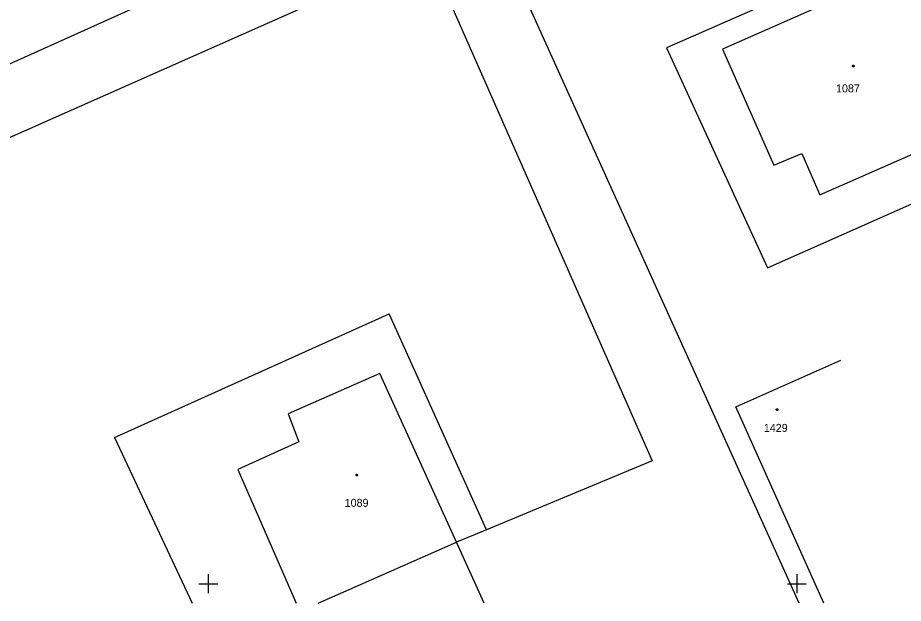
# Model space of a CAD drawing. Extents: x -772300 to -772183, y -1034101 to -1034019.
# Drawn here: x -772258.1 to -772220.48, y -1034100.83 to -1034075.93 of the extents above; entities that cross this region are included whole.
import ezdxf

# ---------------------------------------------------------------- set-up
doc = ezdxf.new("R2010")
doc.units = 0
for name, color, linetype in [('KM_hranice', 7, 'Continuous'), ('KM_kody_budov', 7, 'Continuous'), ('KM_parcelni_cisla', 7, 'Continuous'), ('KM_vnitrni_kresba', 7, 'Continuous'), ('souradnicova_sit', 7, 'Continuous')]:
    doc.layers.add(name, color=color, linetype=linetype)

msp = doc.modelspace()

# ---------------------------------------------------------------- linework, layer by layer
at = {"layer": 'KM_hranice'}
for p, q in [((-772237.52, -1034068.47), (-772299.808, -1034096.549)), ((-772224.901, -1034100.835), (-772237.97, -1034071.91)), ((-772276.27, -1034088.94), (-772240.68, -1034073.14)), ((-772240.68, -1034073.14), (-772231.15, -1034094.77)), ((-772221.31, -1034073.16), (-772230.54, -1034077.22)), ((-772230.54, -1034077.22), (-772226.24, -1034086.57)), ((-772226.24, -1034086.57), (-772217.13, -1034082.52)), ((-772253.98, -1034093.79), (-772242.32, -1034088.53)), ((-772238.18, -1034097.71), (-772242.32, -1034088.53)), ((-772227.59, -1034092.48), (-772223.126, -1034090.49)), ((-772223.857, -1034100.835), (-772227.59, -1034092.48)), ((-772253.98, -1034093.79), (-772250.69, -1034100.835)), ((-772231.15, -1034094.77), (-772238.18, -1034097.71)), ((-772238.18, -1034097.71), (-772239.46, -1034098.24)), ((-772245.329, -1034100.835), (-772239.46, -1034098.24))]:
    msp.add_line(p, q, dxfattribs=at)
at = {"layer": 'KM_kody_budov'}
for points in [[(-772222.6, -1034077.956), (-772222.58, -1034077.96), (-772222.57, -1034077.978), (-772222.566, -1034077.99), (-772222.57, -1034078.008), (-772222.586, -1034078.022), (-772222.6, -1034078.024), (-772222.618, -1034078.018), (-772222.63, -1034078.006), (-772222.634, -1034077.99), (-772222.63, -1034077.972), (-772222.614, -1034077.958)], [(-772225.841, -1034092.565), (-772225.821, -1034092.569), (-772225.811, -1034092.587), (-772225.807, -1034092.599), (-772225.811, -1034092.617), (-772225.827, -1034092.631), (-772225.841, -1034092.633), (-772225.859, -1034092.627), (-772225.871, -1034092.615), (-772225.875, -1034092.599), (-772225.871, -1034092.581), (-772225.855, -1034092.567)], [(-772243.69, -1034095.346), (-772243.67, -1034095.35), (-772243.66, -1034095.368), (-772243.656, -1034095.38), (-772243.66, -1034095.398), (-772243.676, -1034095.412), (-772243.69, -1034095.414), (-772243.708, -1034095.408), (-772243.72, -1034095.396), (-772243.724, -1034095.38), (-772243.72, -1034095.362), (-772243.704, -1034095.348)]]:
    msp.add_lwpolyline(points, close=True, dxfattribs=at)
at = {"layer": 'KM_vnitrni_kresba'}
for p, q in [((-772220.91, -1034074.07), (-772228.15, -1034077.27)), ((-772228.15, -1034077.27), (-772225.98, -1034082.2)), ((-772224.02, -1034083.46), (-772217.91, -1034080.77)), ((-772225.98, -1034082.2), (-772224.78, -1034081.71)), ((-772224.78, -1034081.71), (-772224.02, -1034083.46)), ((-772242.71, -1034091.07), (-772246.6, -1034092.78)), ((-772239.46, -1034098.24), (-772242.71, -1034091.07)), ((-772246.6, -1034092.78), (-772246.15, -1034093.97)), ((-772246.15, -1034093.97), (-772248.74, -1034095.14)), ((-772248.74, -1034095.14), (-772246.26, -1034100.835)), ((-772238.283, -1034100.835), (-772239.46, -1034098.24))]:
    msp.add_line(p, q, dxfattribs=at)
at = {"layer": 'souradnicova_sit'}
for p, q in [((-772250, -1034099.6), (-772250, -1034100.4)), ((-772225, -1034099.6), (-772225, -1034100.4)), ((-772250.4, -1034100), (-772249.6, -1034100)), ((-772225.4, -1034100), (-772224.6, -1034100))]:
    msp.add_line(p, q, dxfattribs=at)

# ---------------------------------------------------------------- texts
at = {"layer": 'KM_parcelni_cisla'}
for s, p in [('1087', (-772223.334, -1034079.11)), ('1429', (-772226.401, -1034093.547)), ('1089', (-772244.206, -1034096.733))]:
    msp.add_text(s, height=0.34, dxfattribs=at).set_placement(p)

doc.saveas('drawing.dxf')
